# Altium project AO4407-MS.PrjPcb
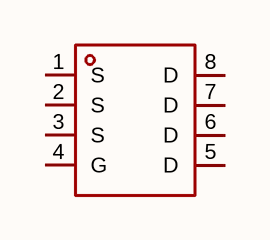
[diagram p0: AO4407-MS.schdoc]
1 sheet, 1 parts. Net scope: global (net labels, ports and power ports of the same name join across sheets).

## Sheet AO4407-MS.schdoc
size 127 x 101 mm

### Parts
Q?  ao4407-ms  [SOP-8_L5.0-W4.0-P1.27-LS6.0-BL]  (value not drawn)

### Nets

Not connected (* = marked no-connect by the designer): Q? 1(S) 2(S) 3(S) 4(G) 5(D) 6(D) 7(D) 8(D)

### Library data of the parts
Q? = ao4407-ms: 数量:1个P沟道;漏源电压(Vdss):30V;连续漏极电流(Id):12A;导通电阻(RDS(on)):9.5mΩ@10V;耗散功率(Pd):2.5W;阈值电压(Vgs(th)):2.5V;; Manufacturer: MSKSEMI(美森科); AddInBom: yes; ModelId: a3315c1c78f949e6bb82c6eaca1c53c7; ModelName: SOP-8_L5.0-W4.0-H1.8-LS6.2-P1.27; ModelTransform: 244.094,196.85,0,90,0,0,0,0,0; Number: 1个P沟道; Drain to Source Voltage: 30V; Current - Continuous Drain(Id): 12A; Pd - Power Dissipation: 2.5W; Gate Threshold Voltage (Vgs(th)): 2.5V; Gate Charge(Qg): 28nC; Input Capacitance(Ciss): 2.94nF; Reverse Transfer Capacitance (Crss@Vds): 210pF; Type: P沟道; Output Capacitance(Coss): 290pF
